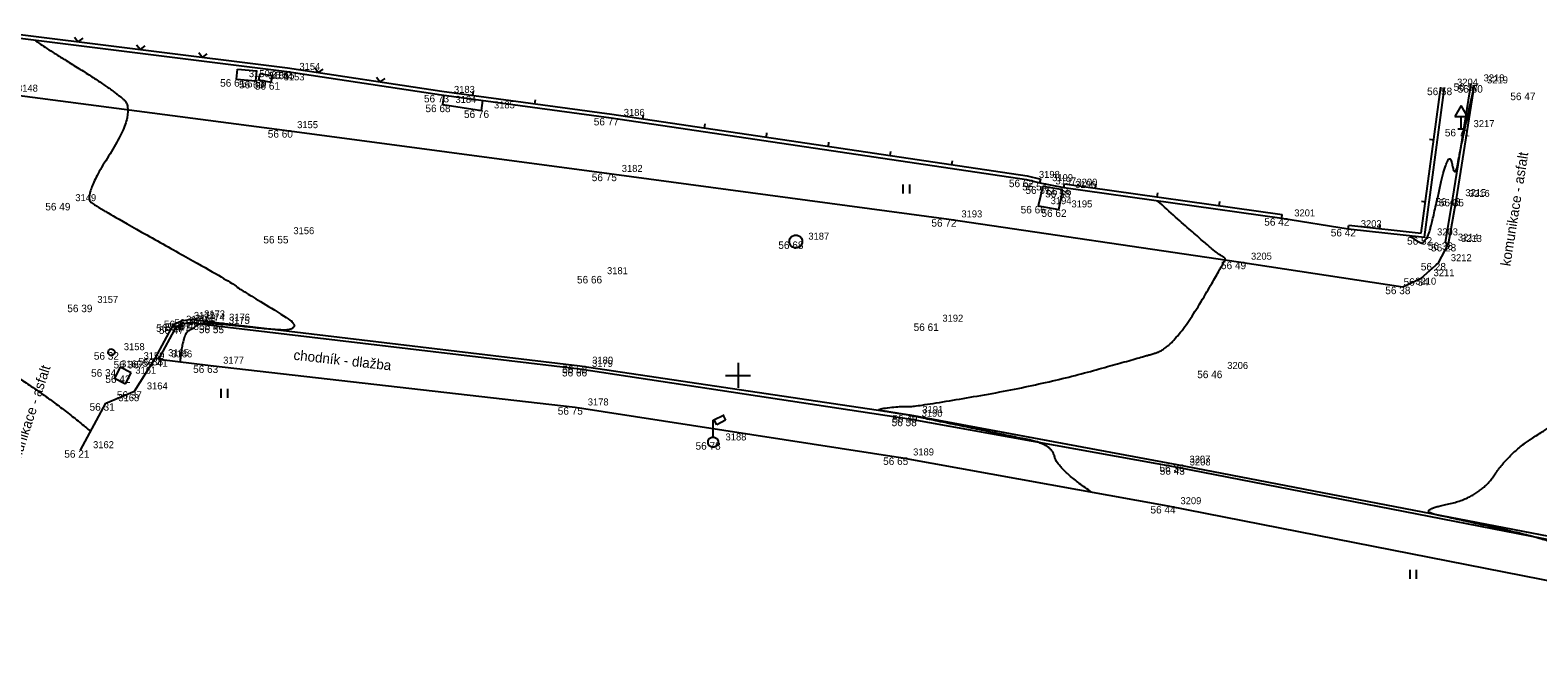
# Model space of a CAD drawing. Extents: x -704017 to -701500, y -1008977 to -1008450.
# Drawn here: x -702328.3 to -702268, y -1008810.8 to -1008786.2 of the extents above; entities that cross this region are included whole.
import ezdxf

# ---------------------------------------------------------------- set-up
doc = ezdxf.new("R2010")
doc.units = 0
for name, color, linetype in [('Z_body', 7, 'Continuous'), ('Z_body_cisla', 7, 'Continuous'), ('Z_body_vysky', 7, 'Continuous'), ('Z_chodnik', 7, 'Continuous'), ('Z_dopravni_znaceni', 7, 'Continuous'), ('Z_hekt_sit', 7, 'Continuous'), ('Z_komunikace', 7, 'Continuous'), ('Z_obruby', 7, 'Continuous'), ('Z_oploceni', 7, 'Continuous'), ('Z_popis', 7, 'Continuous'), ('Z_rozhrani_ploch', 7, 'Continuous'), ('Z_site_znaky_kanalizace', 7, 'Continuous'), ('Z_site_znaky_pilire', 7, 'Continuous'), ('Z_site_znaky_VO', 7, 'Continuous'), ('Z_site_znaky_vodovod', 7, 'Continuous'), ('Z_vrstevnice_vedlejsi', 7, 'Continuous'), ('Z_vstupy', 7, 'Continuous')]:
    doc.layers.add(name, color=color, linetype=linetype)

# ---------------------------------------------------------------- blocks, each defined once
blk = doc.blocks.new('POINT_DISPLAY')
blk.add_line((0, 0), (0, 0))
blk = doc.blocks.new('Z210')
blk.add_line((0, 0), (0, 0.17))
blk = doc.blocks.new('Z212')
for p, q in [((-0.17, 0.17), (0, 0)), ((0, 0), (0.17, 0.17))]:
    blk.add_line(p, q)
blk = doc.blocks.new('Z306')
for p, q in [((-0.13, 0.17), (-0.13, -0.2)), ((0.13, 0.17), (0.13, -0.2))]:
    blk.add_line(p, q)
blk = doc.blocks.new('Z13')
for p, q in [((0, 0.88), (0.45, 1.1)), ((0, 0.2), (0, 0.88)), ((0.15, 0.7), (0.05, 0.9)), ((0.5, 0.88), (0.15, 0.7)), ((0.4, 1.07), (0.5, 0.88)), ((-0.2, 0.05), (-0.15, 0.15)), ((-0.2, -0.05), (-0.2, 0.05)), ((-0.15, 0.15), (-0.05, 0.2)), ((-0.05, 0.2), (0.05, 0.2)), ((0.05, 0.2), (0.15, 0.15)), ((0.15, 0.15), (0.2, 0.05)), ((0.2, 0.05), (0.2, -0.05)), ((-0.15, -0.15), (-0.2, -0.05)), ((-0.05, -0.2), (-0.15, -0.15)), ((0.05, -0.2), (-0.05, -0.2)), ((0.15, -0.15), (0.05, -0.2)), ((0.2, -0.05), (0.15, -0.15))]:
    blk.add_line(p, q)
blk = doc.blocks.new('Z527')
for p, q in [((0, 0.93), (-0.25, 0.5)), ((0.25, 0.5), (0, 0.93)), ((-0.25, 0.5), (0.25, 0.5)), ((-0.13, 0), (0.13, 0)), ((0, 0), (0, 0.5))]:
    blk.add_line(p, q)
blk = doc.blocks.new('Z620')
for p, q in [((-0.25, 0.05), (-0.23, 0.13)), ((-0.25, -0.05), (-0.25, 0.05)), ((-0.23, 0.13), (-0.17, 0.2)), ((-0.17, 0.2), (-0.05, 0.25)), ((-0.05, 0.25), (0.05, 0.25)), ((0.05, 0.25), (0.17, 0.2)), ((0.17, 0.2), (0.23, 0.13)), ((0.23, 0.13), (0.25, 0.05)), ((0.25, 0.05), (0.25, -0.05)), ((-0.2, -0.17), (-0.25, -0.05)), ((-0.13, -0.23), (-0.2, -0.17)), ((-0.05, -0.25), (-0.13, -0.23)), ((0.05, -0.25), (-0.05, -0.25)), ((0.13, -0.23), (0.05, -0.25)), ((0.2, -0.17), (0.13, -0.23)), ((0.25, -0.05), (0.2, -0.17))]:
    blk.add_line(p, q)
blk = doc.blocks.new('Z614')
for p, q in [((-0.13, 0.03), (-0.1, 0.08)), ((-0.13, -0.03), (-0.13, 0.03)), ((-0.1, 0.08), (-0.08, 0.1)), ((-0.08, 0.1), (-0.03, 0.13)), ((-0.03, 0.13), (0.03, 0.13)), ((0.03, 0.13), (0.08, 0.1)), ((0.08, 0.1), (0.1, 0.08)), ((0.1, 0.08), (0.13, 0.03)), ((0.13, 0.03), (0.13, -0.03)), ((-0.1, -0.08), (-0.13, -0.03)), ((-0.08, -0.1), (-0.1, -0.08)), ((-0.03, -0.13), (-0.08, -0.1)), ((0.03, -0.13), (-0.03, -0.13)), ((0.08, -0.1), (0.03, -0.13)), ((0.1, -0.08), (0.08, -0.1)), ((0.13, -0.03), (0.1, -0.08))]:
    blk.add_line(p, q)
blk = doc.blocks.new('Z608')
for p, q in [((0.25, 0.25), (-0.25, 0.25)), ((-0.25, 0.25), (-0.25, -0.25)), ((0.25, -0.25), (0.25, 0.25)), ((-0.25, -0.25), (0.25, -0.25))]:
    blk.add_line(p, q)

msp = doc.modelspace()

# ---------------------------------------------------------------- linework, layer by layer
at = {"layer": 'Z_chodnik'}
for p, q in [((-702323.16, -1008799.35), (-702323.29, -1008799.3)), ((-702323.16, -1008799.35), (-702321.09, -1008799.6)), ((-702321.09, -1008799.6), (-702306.51, -1008801.27)), ((-702306.51, -1008801.27), (-702293.5, -1008803.28)), ((-702293.5, -1008803.28), (-702282.81, -1008805.22)), ((-702282.81, -1008805.22), (-702267.14, -1008808.29))]:
    msp.add_line(p, q, dxfattribs=at)
at = {"layer": 'Z_hekt_sit'}
for p, q in [((-702300, -1008799.5), (-702300, -1008800.5)), ((-702300.5, -1008800), (-702299.5, -1008800))]:
    msp.add_line(p, q, dxfattribs=at)
at = {"layer": 'Z_komunikace'}
for p, q in [((-702329.33, -1008788.72), (-702318.13, -1008790.19)), ((-702271.28, -1008792.94), (-702270.55, -1008788.39)), ((-702318.13, -1008790.19), (-702305.15, -1008791.93)), ((-702305.15, -1008791.93), (-702291.57, -1008793.75)), ((-702271.59, -1008794.74), (-702271.28, -1008792.94)), ((-702291.57, -1008793.75), (-702279.99, -1008795.45)), ((-702272, -1008795.5), (-702271.59, -1008794.74)), ((-702279.99, -1008795.45), (-702273.42, -1008796.45)), ((-702272.69, -1008796.11), (-702272, -1008795.5)), ((-702273.42, -1008796.45), (-702272.69, -1008796.11)), ((-702323.29, -1008799.3), (-702322.57, -1008797.96)), ((-702322.57, -1008797.96), (-702322.26, -1008797.81)), ((-702322.26, -1008797.81), (-702321.85, -1008797.75)), ((-702321.85, -1008797.75), (-702320.85, -1008797.88)), ((-702320.85, -1008797.88), (-702306.33, -1008799.61)), ((-702324.14, -1008800.63), (-702323.29, -1008799.3)), ((-702306.33, -1008799.61), (-702293.13, -1008801.58)), ((-702325.28, -1008801.11), (-702324.14, -1008800.63)), ((-702326.29, -1008802.99), (-702325.28, -1008801.11)), ((-702293.13, -1008801.58), (-702282.45, -1008803.56)), ((-702282.45, -1008803.56), (-702266.82, -1008806.58))]:
    msp.add_line(p, q, dxfattribs=at)
at = {"layer": 'Z_obruby'}
for p, q in [((-702271.42, -1008792.91), (-702270.69, -1008788.32)), ((-702271.72, -1008794.68), (-702271.42, -1008792.91)), ((-702271.72, -1008794.68), (-702271.59, -1008794.74)), ((-702322.46, -1008798.04), (-702322.21, -1008797.92)), ((-702322.21, -1008797.92), (-702321.86, -1008797.88)), ((-702321.86, -1008797.88), (-702320.86, -1008798.01)), ((-702323.16, -1008799.35), (-702322.46, -1008798.04)), ((-702320.86, -1008798.01), (-702306.34, -1008799.74)), ((-702306.34, -1008799.74), (-702293.16, -1008801.73)), ((-702293.16, -1008801.73), (-702282.44, -1008803.67)), ((-702282.44, -1008803.67), (-702266.84, -1008806.71))]:
    msp.add_line(p, q, dxfattribs=at)
at = {"layer": 'Z_oploceni'}
for p, q in [((-702330.12, -1008786.34), (-702318.04, -1008787.85)), ((-702330.1, -1008786.19), (-702318.02, -1008787.7)), ((-702318.02, -1008787.7), (-702311.84, -1008788.63)), ((-702318.04, -1008787.85), (-702311.86, -1008788.78)), ((-702311.86, -1008788.78), (-702305.07, -1008789.7)), ((-702311.84, -1008788.63), (-702305.05, -1008789.55)), ((-702272.68, -1008794.31), (-702271.9, -1008788.47)), ((-702272.55, -1008794.47), (-702271.75, -1008788.49)), ((-702305.05, -1008789.55), (-702288.44, -1008792.02)), ((-702305.07, -1008789.7), (-702288.47, -1008792.17)), ((-702288.47, -1008792.17), (-702287.94, -1008792.3)), ((-702288.44, -1008792.02), (-702287.9, -1008792.15)), ((-702287.94, -1008792.3), (-702287.9, -1008792.15)), ((-702286.97, -1008792.49), (-702286.95, -1008792.34)), ((-702286.97, -1008792.49), (-702278.26, -1008793.71)), ((-702286.95, -1008792.34), (-702278.24, -1008793.56)), ((-702278.26, -1008793.71), (-702278.24, -1008793.56)), ((-702275.6, -1008794.14), (-702275.58, -1008793.99)), ((-702275.6, -1008794.14), (-702272.55, -1008794.47)), ((-702275.58, -1008793.99), (-702272.68, -1008794.31))]:
    msp.add_line(p, q, dxfattribs=at)
at = {"layer": 'Z_rozhrani_ploch'}
for p, q in [((-702287.81, -1008792.44), (-702288, -1008793.22)), ((-702287.02, -1008792.58), (-702287.81, -1008792.44)), ((-702287.17, -1008793.36), (-702287.02, -1008792.58)), ((-702288, -1008793.22), (-702287.17, -1008793.36))]:
    msp.add_line(p, q, dxfattribs=at)
at = {"layer": 'Z_site_znaky_pilire'}
for p, q in [((-702320.06, -1008788.15), (-702320.02, -1008787.75)), ((-702320.02, -1008787.75), (-702319.24, -1008787.82)), ((-702320.06, -1008788.15), (-702319.28, -1008788.22)), ((-702319.28, -1008788.22), (-702319.24, -1008787.82)), ((-702319.16, -1008788.18), (-702319.11, -1008787.93)), ((-702319.16, -1008788.18), (-702318.67, -1008788.27)), ((-702319.11, -1008787.93), (-702318.62, -1008788.02)), ((-702318.67, -1008788.27), (-702318.62, -1008788.02)), ((-702311.8, -1008789.17), (-702311.75, -1008788.8)), ((-702311.8, -1008789.17), (-702310.26, -1008789.4)), ((-702310.26, -1008789.4), (-702310.21, -1008789))]:
    msp.add_line(p, q, dxfattribs=at)
at = {"layer": 'Z_vrstevnice_vedlejsi'}
for points in [[(-702328.107, -1008786.592), (-702327.964, -1008786.728), (-702325.158, -1008788.464), (-702324.025, -1008789.416), (-702326.194, -1008792.835), (-702325.547, -1008793.32), (-702320.263, -1008796.27), (-702319.886, -1008796.583), (-702316.89, -1008798.352), (-702320.854, -1008797.929), (-702321.574, -1008797.917), (-702321.757, -1008798.109), (-702322.203, -1008798.333), (-702322.313, -1008799.452)], [(-702273.16, -1008794.404), (-702272.674, -1008794.753), (-702272.566, -1008794.652), (-702272.504, -1008794.556), (-702272.446, -1008794.496), (-702272.299, -1008794.123), (-702271.574, -1008790.847), (-702271.337, -1008792.218), (-702271.055, -1008790.615), (-702270.55, -1008788.39)], [(-702285.864, -1008804.666), (-702287.246, -1008803.724), (-702287.443, -1008802.765), (-702289.265, -1008802.395), (-702293.133, -1008801.597), (-702293.907, -1008801.472), (-702294.597, -1008801.361), (-702293.37, -1008801.215), (-702293.063, -1008801.275), (-702287.983, -1008800.402), (-702283.977, -1008799.306), (-702282.575, -1008798.878), (-702280.493, -1008795.376), (-702280.542, -1008795.289), (-702280.987, -1008795.027), (-702283.237, -1008793.013)], [(-702255.5, -1008810.815), (-702261.999, -1008809.278), (-702263.547, -1008808.631), (-702266.89, -1008806.973), (-702267.661, -1008806.55), (-702271.194, -1008805.765), (-702272.898, -1008805.406), (-702270.35, -1008804.888), (-702269.13, -1008803.035), (-702266.894, -1008801.685), (-702267.126, -1008801.33), (-702266.017, -1008799.003), (-702264.87, -1008797.45), (-702251.244, -1008799.459), (-702250.211, -1008798.511), (-702249.863, -1008798.464)], [(-702330.685, -1008799.077), (-702330.56, -1008798.954), (-702327.299, -1008801.039), (-702325.886, -1008802.238)]]:
    msp.add_open_spline(points, degree=2, dxfattribs=at)
at = {"layer": 'Z_vstupy'}
for p, q in [((-702287.94, -1008792.3), (-702286.97, -1008792.49)), ((-702278.26, -1008793.71), (-702275.6, -1008794.14))]:
    msp.add_line(p, q, dxfattribs=at)

# ---------------------------------------------------------------- block references
at = {"layer": 'Z_body'}
for p in [(-702320.06, -1008788.15), (-702319.28, -1008788.22), (-702319.16, -1008788.18), (-702318.67, -1008788.27), (-702318.04, -1008787.85), (-702270.69, -1008788.32), (-702311.86, -1008788.78), (-702271.75, -1008788.49), (-702270.55, -1008788.39), (-702268.42, -1008788.69), (-702311.8, -1008789.17), (-702310.26, -1008789.4), (-702305.07, -1008789.7), (-702271.09, -1008790.14), (-702318.13, -1008790.19), (-702305.15, -1008791.93), (-702288.47, -1008792.17), (-702287.94, -1008792.3), (-702287.81, -1008792.44), (-702286.97, -1008792.49), (-702327, -1008793.1), (-702287.02, -1008792.58), (-702271.42, -1008792.91), (-702271.28, -1008792.94), (-702291.57, -1008793.75), (-702288, -1008793.22), (-702287.17, -1008793.36), (-702278.26, -1008793.71), (-702275.6, -1008794.14), (-702318.28, -1008794.42), (-702297.69, -1008794.64), (-702272.55, -1008794.47), (-702271.72, -1008794.68), (-702271.59, -1008794.74), (-702279.99, -1008795.45), (-702272, -1008795.5), (-702305.74, -1008796.02), (-702272.69, -1008796.11), (-702273.42, -1008796.45), (-702326.12, -1008797.17), (-702322.57, -1008797.96), (-702322.26, -1008797.81), (-702322.21, -1008797.92), (-702321.86, -1008797.88), (-702321.85, -1008797.75), (-702320.85, -1008797.88), (-702292.33, -1008797.92), (-702322.46, -1008798.04), (-702320.86, -1008798.01), (-702325.06, -1008799.07), (-702325.17, -1008799.75), (-702324.27, -1008799.42), (-702323.29, -1008799.3), (-702323.16, -1008799.35), (-702321.09, -1008799.6), (-702306.34, -1008799.74), (-702306.33, -1008799.61), (-702324.6, -1008800), (-702280.94, -1008799.81), (-702324.14, -1008800.63), (-702325.28, -1008801.11), (-702306.51, -1008801.27), (-702293.13, -1008801.58), (-702293.16, -1008801.73), (-702301, -1008802.67), (-702326.29, -1008802.99), (-702293.5, -1008803.28), (-702282.45, -1008803.56), (-702282.44, -1008803.67), (-702282.81, -1008805.22)]:
    msp.add_blockref('POINT_DISPLAY', p, dxfattribs=at)
at = {"layer": 'Z_dopravni_znaceni'}
msp.add_blockref('Z527', (-702271.09, -1008790.14), dxfattribs=at)
at = {"layer": 'Z_oploceni'}
for name, p, rotation in [('Z212', (-702326.38, -1008786.66), -7.10000000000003), ('Z212', (-702323.9, -1008786.97), -7.10000000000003), ('Z212', (-702321.42, -1008787.28), -7.10000000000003), ('Z212', (-702316.78, -1008787.89), -8.600000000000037), ('Z212', (-702314.31, -1008788.26), -8.600000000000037), ('Z210', (-702310.6, -1008788.8), -7.699999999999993), ('Z210', (-702308.12, -1008789.14), -7.699999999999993), ('Z210', (-702303.81, -1008789.74), -8.499999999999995), ('Z210', (-702301.34, -1008790.1), -8.499999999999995), ('Z210', (-702298.87, -1008790.47), -8.499999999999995), ('Z210', (-702296.39, -1008790.84), -8.499999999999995), ('Z210', (-702272.18, -1008790.59), 82.4), ('Z210', (-702293.92, -1008791.21), -8.499999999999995), ('Z210', (-702291.45, -1008791.58), -8.499999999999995), ('Z210', (-702285.71, -1008792.51), -8.000000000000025), ('Z210', (-702283.24, -1008792.86), -8.000000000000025), ('Z210', (-702280.76, -1008793.21), -8.000000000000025), ('Z210', (-702272.51, -1008793.07), 82.4), ('Z210', (-702274.34, -1008794.13), -6.199999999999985)]:
    msp.add_blockref(name, p, dxfattribs=dict(at, rotation=rotation))
at = {"layer": 'Z_popis'}
for p in [(-702293.28, -1008792.53), (-702320.55, -1008800.7), (-702273.01, -1008807.94)]:
    msp.add_blockref('Z306', p, dxfattribs=at)
at = {"layer": 'Z_site_znaky_kanalizace'}
msp.add_blockref('Z620', (-702297.69, -1008794.64), dxfattribs=at)
at = {"layer": 'Z_site_znaky_VO'}
msp.add_blockref('Z13', (-702301, -1008802.67), dxfattribs=at)
at = {"layer": 'Z_site_znaky_vodovod'}
for name, p, rotation in [('Z614', (-702325.06, -1008799.07), 10.799999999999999), ('Z608', (-702324.6, -1008800), -27.000000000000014)]:
    msp.add_blockref(name, p, dxfattribs=dict(at, rotation=rotation))

# ---------------------------------------------------------------- texts
at = {"layer": 'Z_body_cisla'}
for s, p in [('3154', (-702317.54, -1008787.78)), ('3150', (-702319.56, -1008788.07)), ('3151', (-702318.78, -1008788.15)), ('3152', (-702318.66, -1008788.11)), ('3153', (-702318.17, -1008788.2)), ('3204', (-702271.25, -1008788.41)), ('3218', (-702270.19, -1008788.24)), ('3219', (-702270.05, -1008788.32)), ('3148', (-702328.83, -1008788.65)), ('3183', (-702311.36, -1008788.7)), ('3184', (-702311.3, -1008789.1)), ('3185', (-702309.76, -1008789.32)), ('3186', (-702304.57, -1008789.62)), ('3155', (-702317.63, -1008790.11)), ('3217', (-702270.59, -1008790.07)), ('3182', (-702304.65, -1008791.86)), ('3198', (-702287.97, -1008792.1)), ('3199', (-702287.44, -1008792.23)), ('3197', (-702287.31, -1008792.36)), ('3196', (-702286.52, -1008792.5)), ('3200', (-702286.47, -1008792.41)), ('3215', (-702270.92, -1008792.83)), ('3149', (-702326.5, -1008793.03)), ('3194', (-702287.5, -1008793.15)), ('3195', (-702286.67, -1008793.28)), ('3216', (-702270.78, -1008792.86)), ('3193', (-702291.07, -1008793.68)), ('3201', (-702277.76, -1008793.64)), ('3156', (-702317.78, -1008794.35)), ('3187', (-702297.19, -1008794.57)), ('3202', (-702275.1, -1008794.07)), ('3203', (-702272.05, -1008794.4)), ('3214', (-702271.22, -1008794.61)), ('3213', (-702271.09, -1008794.66)), ('3205', (-702279.49, -1008795.37)), ('3212', (-702271.5, -1008795.43)), ('3181', (-702305.24, -1008795.95)), ('3210', (-702272.92, -1008796.37)), ('3211', (-702272.19, -1008796.03)), ('3157', (-702325.62, -1008797.1)), ('3173', (-702321.35, -1008797.68)), ('3170', (-702322.07, -1008797.89)), ('3167', (-702321.96, -1008797.96)), ('3172', (-702321.76, -1008797.74)), ('3168', (-702321.71, -1008797.85)), ('3174', (-702321.36, -1008797.81)), ('3175', (-702320.36, -1008797.94)), ('3176', (-702320.35, -1008797.81)), ('3192', (-702291.83, -1008797.85)), ('3158', (-702324.56, -1008798.99)), ('3159', (-702323.77, -1008799.35)), ('3165', (-702322.79, -1008799.23)), ('3166', (-702322.66, -1008799.28)), ('3160', (-702324.67, -1008799.68)), ('3161', (-702324.1, -1008799.93)), ('3177', (-702320.59, -1008799.53)), ('3179', (-702305.84, -1008799.66)), ('3180', (-702305.83, -1008799.53)), ('3206', (-702280.44, -1008799.74)), ('3164', (-702323.64, -1008800.56)), ('3163', (-702324.78, -1008801.03)), ('3178', (-702306.01, -1008801.2)), ('3190', (-702292.66, -1008801.65)), ('3191', (-702292.63, -1008801.5)), ('3162', (-702325.79, -1008802.91)), ('3188', (-702300.5, -1008802.6)), ('3189', (-702293, -1008803.2)), ('3207', (-702281.95, -1008803.49)), ('3208', (-702281.94, -1008803.6)), ('3209', (-702282.31, -1008805.15))]:
    msp.add_text(s, height=0.28, dxfattribs=at).set_placement(p)
at = {"layer": 'Z_body_vysky'}
for s, p in [('56 61', (-702320.71, -1008788.45)), ('56 60', (-702319.955, -1008788.52)), ('56 59', (-702319.86, -1008788.48)), ('56 61', (-702319.32, -1008788.57)), ('56 65', (-702318.74, -1008788.15)), ('56 57', (-702271.39, -1008788.62)), ('56 73', (-702312.56, -1008789.08)), ('56 58', (-702272.45, -1008788.79)), ('56 50', (-702271.225, -1008788.69)), ('56 47', (-702269.12, -1008788.99)), ('56 68', (-702312.5, -1008789.47)), ('56 76', (-702310.96, -1008789.7)), ('56 77', (-702305.77, -1008790)), ('56 71', (-702271.74, -1008790.44)), ('56 60', (-702318.805, -1008790.49)), ('56 75', (-702305.85, -1008792.23)), ('56 62', (-702289.17, -1008792.47)), ('56 54', (-702288.64, -1008792.6)), ('56 57', (-702288.51, -1008792.74)), ('56 56', (-702287.67, -1008792.79)), ('56 49', (-702327.7, -1008793.4)), ('56 58', (-702287.72, -1008792.88)), ('56 43', (-702272.12, -1008793.21)), ('56 35', (-702271.98, -1008793.24)), ('56 72', (-702292.27, -1008794.05)), ('56 66', (-702288.7, -1008793.52)), ('56 62', (-702287.87, -1008793.66)), ('56 42', (-702278.96, -1008794.01)), ('56 42', (-702276.3, -1008794.44)), ('56 55', (-702318.98, -1008794.72)), ('56 68', (-702298.39, -1008794.94)), ('56 52', (-702273.25, -1008794.77)), ('56 36', (-702272.42, -1008794.98)), ('56 28', (-702272.29, -1008795.04)), ('56 49', (-702280.69, -1008795.75)), ('56 28', (-702272.7, -1008795.8)), ('56 66', (-702306.44, -1008796.32)), ('56 34', (-702273.39, -1008796.41)), ('56 38', (-702274.12, -1008796.75)), ('56 39', (-702326.82, -1008797.47)), ('56 44', (-702323.27, -1008798.26)), ('56 44', (-702322.96, -1008798.11)), ('56 47', (-702322.91, -1008798.22)), ('56 48', (-702322.56, -1008798.18)), ('56 46', (-702322.55, -1008798.05)), ('56 47', (-702321.55, -1008798.18)), ('56 61', (-702292.98, -1008798.22)), ('56 47', (-702323.16, -1008798.34)), ('56 55', (-702321.56, -1008798.31)), ('56 32', (-702325.76, -1008799.37)), ('56 34', (-702325.87, -1008800.05)), ('56 36', (-702324.97, -1008799.72)), ('56 38', (-702323.99, -1008799.6)), ('56 41', (-702323.81, -1008799.65)), ('56 63', (-702321.79, -1008799.9)), ('56 66', (-702307.04, -1008800.04)), ('56 58', (-702307.03, -1008799.91)), ('56 46', (-702281.64, -1008800.11)), ('56 42', (-702325.3, -1008800.3)), ('56 37', (-702324.84, -1008800.93)), ('56 31', (-702325.93, -1008801.41)), ('56 75', (-702307.21, -1008801.57)), ('56 49', (-702293.83, -1008801.88)), ('56 58', (-702293.86, -1008802.03)), ('56 78', (-702301.7, -1008802.97)), ('56 21', (-702326.94, -1008803.29)), ('56 65', (-702294.2, -1008803.58)), ('56 36', (-702283.15, -1008803.86)), ('56 43', (-702283.14, -1008803.97)), ('56 44', (-702283.51, -1008805.52))]:
    msp.add_text(s, height=0.3, dxfattribs=at).set_placement(p)
at = {"layer": 'Z_popis'}
for s, rotation, p in [('komunikace - asfalt', 81, (-702269.12, -1008795.65)), ('chodník - dlažba', 353.7, (-702317.79, -1008799.37)), ('komunikace - asfalt', 72, (-702328.91, -1008804.05))]:
    msp.add_text(s, height=0.4, rotation=rotation, dxfattribs=at).set_placement(p)

doc.saveas('drawing.dxf')
